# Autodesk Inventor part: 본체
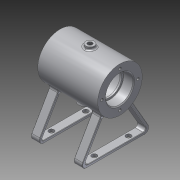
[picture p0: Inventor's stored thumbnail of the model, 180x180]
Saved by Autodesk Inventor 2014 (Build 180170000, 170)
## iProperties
Created: 2016-03
Part Number: 본체
Material: 알루미늄 6061
Document SubType Name: Modeling
Designer: basic
Density: 2.71 g/cm^3
Appearance: 알루미늄 - 평지
Mass: 213.519 g
Surface Area: 333.701 cm^2
Volume: 78.7893 cm^3
Author: basic
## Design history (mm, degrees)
sketch "스케치2"
  geometry: L1 (35, 65)-(-35, 65); L2 (35, 65)-(35, 91); L3 (35, 91)-(-35, 91); L4 (-35, 91)-(-35, 65); L5 (35, 81)-(23, 81); L6 (23, 81)-(23, 79); L7 (23, 79)-(21, 79); L8 (21, 79)-(21, 86); L9 (21, 86)-(-21, 86); L10 (-21, 86)-(-21, 79); L11 (-21, 79)-(-23, 79); L12 (-23, 79)-(-23, 81); L13 (-23, 81)-(-35, 81); 2 further points
  constraints: 26 end point, 7 parallel, 5 perpendicular, 4 equal length, 2 point on line, 1 horizontal, 1 midpoint, 1 vertical alignment
  dimensions: "d2" = 70 distance of L1.start L1.end; "d3" = 65 distance from line of point (0, 0) L1; "d4" = 14 distance between parallel lines of L1 L7; "d5" = 26 distance between parallel lines of L1 L3; "d6" = 21 distance between parallel lines of L1 L9; "d7" = 16 distance between parallel lines of L1 L5; "d8" = 42 distance between parallel lines of L10 L8; "d9" = 12 distance between parallel lines of L2 L6
revolve "회전1" sketch "스케치2" stored, may be unused: angle "d10" = 90 deg
fillet "모깎기1" dims "d11" = 0.3
chamfer "모따기1" distance "d12" = 1; stored, may be unused: second distance "d13" = 2, angle "d14" = 45 deg
chamfer "모따기2" distance "d15" = 1; stored, may be unused: second distance "d16" = 2, angle "d17" = 45 deg
fillet "모깎기2" dims "d24" = 3
node "작업 평면1"
sketch "스케치6"
  geometry: L1 (-42.594, 0)-(42.594, 0); L2 (-16.613, 45)-(-42.594, 0); L3 (16.613, 45)-(42.594, 0); L4 (0, 65)-(0, 0); L5 (-14.015, 43.5)-(-37.398, 3); L6 (-37.398, 3)-(37.398, 3); L7 (37.398, 3)-(14.015, 43.5); C1 r 20.236 at (0, 65) reference; A1 r 26 centre (0, 65) between (-16.613, 45) and (16.613, 45) reference; A2 r 26 centre (0, 65) between (-16.613, 45) and (-14.183, 43.209); A3 r 26 centre (0, 65) between (14.183, 43.209) and (16.613, 45); 1 further point
  constraints: 14 end point, 6 point on circle, 2 centre point, 2 coincident, 2 point on line, 1 equal length, 1 horizontal, 1 midpoint, 1 perpendicular, 2 other
  dimensions: "d26" = 30 deg angle of L4 L2; "d27" = 30 deg angle of L3 L4; "d28" = 45 distance from line of L1 L3.start; "d29" = 3 distance between parallel lines of L2 L5
extrude "돌출1" join sketch "스케치6" distance "d30" = 10; taper "d31" = 0 deg
fillet "모깎기3" dims "d32" = 5
fillet "모깎기4" dims "d33" = 3
fillet "모깎기5" dims "d34" = 0.5
fillet "모깎기6" dims "d35" = 3
sketch "스케치7" dims "d36" = 42
  geometry: L1 (0, 0)-(0, -21); C1 r 17 at (0, 0) reference; 2 further points
  constraints: 2 coincident, 2 end point, 1 vertical, 1 vertical alignment, 2 other
hole "구멍1" sketch "스케치7" at (0, -21) diameter "d37" = 3.242; stored, may be unused: countersink angle "d41" = 90 deg, drill point angle "d43" = 118 deg; dims "d38" = 8, "d39" = 4, "d40" = 2, "d42" = 10
node "작업 평면2"
sketch "스케치8"
  geometry: C1 r 5 at (0, 0); 1 further point
  constraints: 1 centre point, 1 coincident
  dimensions: "d48" = 10 diameter of C1
extrude "돌출2" join sketch "스케치8" stored distance "d49" = 10; taper "d50" = 0 deg
fillet "모깎기7" dims "d51" = 2
sketch "스케치9"
  geometry: C1 r 5 at (0, 0) reference; 1 further point
  constraints: 1 coincident
hole "구멍2" sketch "스케치9" at (0, 0) diameter "d52" = 5.188; stored, may be unused: countersink angle "d56" = 90 deg, drill point angle "d58" = 118 deg; dims "d53" = 20, "d54" = 4, "d55" = 2, "d57" = 10
node "작업 평면5"
sketch "스케치12"
  geometry: L1 (-35, 0)-(35, 0) reference; L2 (-20.5, -42.258)-(-29.5, -42.258) reference; L3 (-30, -41.258)-(-30, -37.258) reference; L4 (-29.5, -36.258)-(-20.5, -36.258) reference; L5 (-20, -37.258)-(-20, -41.258) reference; L6 (-20, -62.5)-(-20, -64.5) reference; L7 (-20.5, -65)-(-29.5, -65) reference; L8 (-30, -64.5)-(-30, -62.5) reference; L9 (-29.5, -62)-(-20.5, -62) reference; L10 (-35, -26)-(-35, 26) reference; L11 (-35, 0)-(35, 0) reference; L12 (-20.5, -42.258)-(-29.5, -42.258) reference; L13 (-30, -41.258)-(-30, -37.258) reference; L14 (-29.5, -36.258)-(-20.5, -36.258) reference; L15 (-20, -37.258)-(-20, -41.258) reference; L16 (-20, -62.5)-(-20, -64.5) reference; L17 (-20.5, -65)-(-29.5, -65) reference; L18 (-30, -64.5)-(-30, -62.5) reference; L19 (-29.5, -62)-(-20.5, -62) reference; L20 (30, -42.258)-(20, -42.258) reference; L21 (20, -42.258)-(20, -36.258) reference; L22 (20, -36.258)-(30, -36.258) reference; L23 (30, -36.258)-(30, -42.258) reference; L24 (30, -62)-(30, -65) reference; L25 (30, -65)-(20, -65) reference; L26 (20, -65)-(20, -62) reference; L27 (20, -62)-(30, -62) reference; L28 (30, -42.258)-(20, -42.258) reference; L29 (20, -42.258)-(20, -36.258) reference; L30 (20, -36.258)-(30, -36.258) reference; L31 (30, -36.258)-(30, -42.258) reference; L32 (30, -62)-(30, -65) reference; L33 (30, -65)-(20, -65) reference; L34 (20, -65)-(20, -62) reference; L35 (20, -62)-(30, -62) reference; A1 r 0.5 centre (-20.5, -64.5) between (-20.5, -65) and (-20, -64.5) reference; A2 r 0.5 centre (-29.5, -64.5) between (-30, -64.5) and (-29.5, -65) reference; A3 r 0.5 centre (-29.5, -62.5) between (-29.5, -62) and (-30, -62.5) reference; A4 r 0.5 centre (-20.5, -62.5) between (-20, -62.5) and (-20.5, -62) reference; A5 r 0.5 centre (-20.5, -64.5) between (-20.5, -65) and (-20, -64.5) reference; A6 r 0.5 centre (-29.5, -64.5) between (-30, -64.5) and (-29.5, -65) reference; A7 r 0.5 centre (-29.5, -62.5) between (-29.5, -62) and (-30, -62.5) reference; A8 r 0.5 centre (-20.5, -62.5) between (-20, -62.5) and (-20.5, -62) reference; 10 further points; 8 other entities
  constraints: 9 other
  dimensions: "d61" = 35 distance from line of L10 point (0, 0); "d62" = 26 vertical distance of point (0, 0) L10.end
feature "엠보싱1" sketch "스케치12" dims "d2" = 70, "d3" = 65, "d4" = 14, "d5" = 26, "d6" = 21, "d7" = 16, "d8" = 42, "d9" = 12, "d63" = 0.5, "d64" = 0
sketch "스케치15"
  geometry: L1 (-2.594, 94)-(-2.594, 85.839) reference; L2 (2.594, 85.839)-(2.594, 94) reference; L3 (2.594, 94)-(5, 94) reference; L4 (5, 94)-(5, 92.111) reference; L5 (25.891, 67.381)-(26.389, 67.427) reference; L6 (26.424, 67.007)-(25.925, 66.969) reference; L7 (-5, 92.111)-(-5, 94) reference; L8 (-5, 94)-(-2.594, 94) reference; L9 (0, 65)-(0, 39); L10 (0, 65)-(-6.729, 39.886); A1 r 21 centre (0, 65) between (-2.594, 85.839) and (2.594, 85.839) reference; A2 r 26 centre (0, 65) between (25.891, 67.381) and (6.5, 90.174) reference; A3 r 26.5 centre (0, 65) between (26.424, 67.007) and (26.389, 67.427) reference; A4 r 26 centre (0, 65) between (-6.5, 90.174) and (25.925, 66.969) reference; 1 further point
  constraints: 4 end point, 2 point on circle, 1 perpendicular, 2 other
  dimensions: "d70" = 15 deg angle of L9 L10
  node "절단 모서리 투영7"
node "작업 평면7"
sketch "스케치16"
  geometry: C1 r 6 at (0, 0); 1 further point
  constraints: 1 centre point
  dimensions: "d71" = 12 diameter of C1
extrude "돌출3" join sketch "스케치16" stored distance "d72" = 10; taper "d73" = 0 deg
sketch "스케치17"
  geometry: C1 r 6 at (0, 0); A1 r 6 centre (0, 0) between (-6, 0) and (6, 0) reference; 1 further point
  constraints: 1 centre point, 1 coincident
  dimensions: "d74" = 12 diameter of C1
extrude "돌출4" join sketch "스케치17" distance "d75" = 3; taper "d76" = 0 deg
fillet "모깎기8" dims "d77" = 2
sketch "스케치18"
  geometry: C1 r 6 at (0, 0) reference; 2 further points
  constraints: 1 coincident
hole "구멍3" sketch "스케치18" at (0, 0) diameter "d78" = 5.188; stored, may be unused: countersink angle "d82" = 90 deg, drill point angle "d84" = 118 deg; dims "d79" = 20, "d80" = 4, "d81" = 2, "d83" = 10
fillet "모깎기10" dims "d106" = 5
fillet "모깎기13" dims "d109" = 2
fillet "모깎기14" dims "d110" = 0.5
fillet "모깎기15" dims "d111" = 3
sketch "스케치21"
  geometry: L1 (-0.5, 69.368)-(-0.5, 71.899) reference; L2 (0, 72.45)-(9, 72.45) reference; L3 (9.5, 71.899)-(9.5, 69.368) reference; L4 (9, 67.868)-(9, 0) reference; L5 (0, 0)-(9, 0) reference; L6 (-0.5, -4.031)-(-0.5, -1.5) reference; L7 (9, -4.583)-(0, -4.583) reference; L8 (9.5, -1.5)-(9.5, -4.031) reference; L9 (0, 67.868)-(9, 67.868) reference; L10 (0, 67.868)-(0, 0) reference; L11 (49.5, 67.938)-(49.5, 71.899) reference; L12 (50, 72.45)-(59, 72.45) reference; L13 (59.5, 71.899)-(59.5, 67.938) reference; L14 (59, 66.135)-(59, 1.732) reference; L15 (59, 1.732)-(50, 1.732) reference; L16 (49.5, -4.031)-(49.5, -0.071) reference; L17 (59, -4.583)-(50, -4.583) reference; L18 (59.5, -0.071)-(59.5, -4.031) reference; L19 (59, 66.135)-(50, 66.135) reference; L20 (50, 66.135)-(50, 1.732) reference; C1 r 3 at (4.5, 53.934); C2 r 3 at (4.5, 13.934); C3 r 3 at (54.5, 53.934); C4 r 3 at (54.5, 13.934); 4 further points
  constraints: 4 centre point, 4 vertical alignment, 3 midpoint, 16 other
  dimensions: "d112" = 6 diameter of C1; "d113" = 6 diameter of C2; "d114" = 6 diameter of C3; "d115" = 6 diameter of C4; "d116" = 20 vertical distance of point (29.5, 33.934) C1.centre; "d117" = 40 distance of C1.centre C2.centre; "d118" = 20 vertical distance of point (29.5, 33.934) C3.centre; "d119" = 40 distance of C4.centre C3.centre
extrude "돌출7" cut sketch "스케치21" stored distance "d120" = 3; taper "d121" = 0 deg
node "솔리드1"
mirror "대칭1"
pattern_circular "원형 패턴1" dims angle "d45" = 360 deg
mirror "대칭2"
node "절단 모서리 투영1"
node "절단 모서리 투영4"
node "절단 모서리 투영5"
node "절단 모서리 투영10"
other parameters: "d47" = 94
